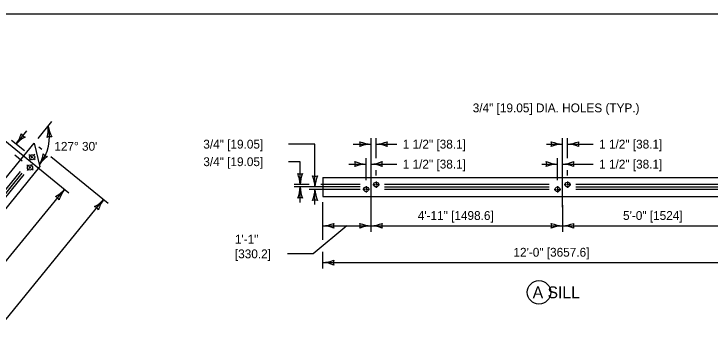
# Model space of a CAD drawing. Extents: x 49991.4 to 50021, y 49987.6 to 50011.4.
# Drawn here: x 50009.55 to 50014.286, y 49996.888 to 49998.999 of the extents above; entities that cross this region are included whole.
import ezdxf

# ---------------------------------------------------------------- set-up
doc = ezdxf.new("R2010")
doc.units = 0
for name, color, linetype in [('Level 1', 7, 'Continuous'), ('Level 2', 7, 'Continuous'), ('Level 3', 7, 'Continuous'), ('Level 5', 7, 'Continuous')]:
    doc.layers.add(name, color=color, linetype=linetype)

msp = doc.modelspace()

# ---------------------------------------------------------------- linework, layer by layer
at = {"layer": 'Level 1'}
for p, q in [((50007.4465, 49995.3728), (50009.6889, 49998.1205)), ((50009.6889, 49998.1205), (50009.7272, 49997.9577)), ((50007.5494, 49995.2888), (50009.7272, 49997.9577)), ((50007.6228, 49995.51), (50009.5947, 49997.926)), ((50007.6356, 49995.4996), (50009.6075, 49997.9156)), ((50007.6486, 49995.489), (50009.6203, 49997.9052)), ((50011.6513, 49997.8849), (50014.9124, 49997.8849)), ((50011.6513, 49997.8849), (50011.6513, 49997.7571)), ((50013.1902, 49997.8371), (50012.0707, 49997.8371)), ((50012.0707, 49997.8211), (50013.1902, 49997.8211)), ((50014.5603, 49997.8371), (50013.3735, 49997.8371)), ((50013.3735, 49997.8211), (50014.5603, 49997.8211)), ((50013.1902, 49997.8051), (50012.0707, 49997.8051)), ((50014.5603, 49997.8051), (50013.3735, 49997.8051)), ((50011.6513, 49997.7571), (50014.9124, 49997.7571))]:
    msp.add_line(p, q, dxfattribs=at)
msp.add_lwpolyline([(49999.3835, 49998.9992), (50016.7501, 49998.9992), (50016.7501, 49987.7988), (49999.3835, 49987.7988)], close=True, dxfattribs=at)
for centre in [(50009.6742, 49998.0234), (50009.6597, 49997.9536)]:
    msp.add_circle(centre, 0.0175, dxfattribs=at)
for centre in [(50011.9465, 49997.8052), (50012.0137, 49997.837), (50013.2479, 49997.8051), (50013.3158, 49997.837)]:
    msp.add_ellipse(centre, major_axis=(0.017, 0), ratio=0.940299, dxfattribs=at)
at = {"layer": 'Level 2'}
msp.add_circle((50013.1221, 49997.1041), 0.08, dxfattribs=at)
at = {"layer": 'Level 3'}
for p, q in [((50009.7142, 49998.1515), (50009.8086, 49998.2671)), ((50009.5648, 49998.1128), (50009.6385, 49998.2032)), ((50009.9245, 49997.7786), (50009.4364, 49998.1768)), ((50011.9797, 49997.5168), (50011.9797, 49998.1527)), ((50012.0136, 49998.0167), (50012.0136, 49998.1527)), ((50013.2819, 49997.9099), (50013.2819, 49998.1527)), ((50013.3159, 49998.0167), (50013.3159, 49998.1527)), ((50009.6219, 49998.0662), (50009.5339, 49998.1381)), ((50011.5984, 49998.1127), (50011.4187, 49998.1127)), ((50011.5984, 49997.9146), (50011.5984, 49998.1127)), ((50011.8575, 49998.1127), (50011.9797, 49998.1127)), ((50012.0136, 49998.1127), (50012.1551, 49998.1127)), ((50013.1729, 49998.1127), (50013.2819, 49998.1127)), ((50013.3159, 49998.1127), (50013.4911, 49998.1127)), ((50009.7199, 49998.0952), (50009.7402, 49998.0786)), ((50009.6074, 49997.9964), (50009.5559, 49998.0385)), ((50009.8022, 49998.028), (50010.1915, 49997.7104)), ((50011.9464, 49997.8664), (50011.9464, 49998.0167)), ((50013.2479, 49997.8664), (50013.2479, 49998.0167)), ((50011.4974, 49997.9931), (50011.4187, 49997.9931)), ((50011.4974, 49997.8371), (50011.4974, 49997.9931)), ((50011.8276, 49997.9767), (50011.9464, 49997.9767)), ((50011.9797, 49997.9767), (50012.1551, 49997.9767)), ((50013.1411, 49997.9767), (50013.2479, 49997.9767)), ((50013.2819, 49997.9767), (50013.4911, 49997.9767)), ((50011.5984, 49997.8211), (50011.5984, 49997.9146)), ((50012.0136, 49997.8983), (50012.0136, 49997.9367)), ((50013.2819, 49997.6836), (50013.2819, 49997.9099)), ((50013.3159, 49997.8983), (50013.3159, 49997.9367)), ((50011.5584, 49997.8371), (50011.4574, 49997.8371)), ((50011.9064, 49997.8211), (50011.4574, 49997.8211)), ((50011.4974, 49997.7156), (50011.4974, 49997.8211)), ((50011.9064, 49997.8371), (50011.6384, 49997.8371)), ((50007.8012, 49995.24), (50009.8935, 49997.8039)), ((50011.9064, 49997.8051), (50011.5584, 49997.8051)), ((50011.5984, 49997.7012), (50011.5984, 49997.8051)), ((50007.918, 49994.9878), (50010.1605, 49997.7357)), ((50011.6513, 49997.4608), (50011.6513, 49997.7171)), ((50013.2819, 49997.698), (50013.2819, 49997.5168)), ((50011.6513, 49997.5568), (50011.9797, 49997.5568)), ((50011.9797, 49997.5568), (50013.2819, 49997.5568)), ((50013.2819, 49997.5568), (50014.6407, 49997.5568)), ((50011.6513, 49997.2668), (50011.6513, 49997.3808)), ((50011.6513, 49997.3068), (50014.9124, 49997.3068))]:
    msp.add_line(p, q, dxfattribs=at)
msp.add_lwpolyline([(50011.8155, 49997.5568), (50011.585, 49997.3659), (50011.4116, 49997.3659)], dxfattribs=at)
for centre, radius, start, end in [((50009.5617, 49998.2185), 0.2223, 344.3666, 4.5501), ((50010.0129, 49998.2755), 0.233, 189.7379, 208.9878), ((50009.3772, 49998.251), 0.233, 323.6381, 342.888), ((50009.7312, 49997.9654), 0.2223, 118.2668, 138.4503), ((50009.6458, 49998.2122), 0.0548, 212.9496, 248.672), ((50009.7987, 49998.1088), 0.0548, 79.0494, 114.7718), ((50011.9889, 49998.3348), 0.2223, 247.456, 267.6395), ((50011.8515, 49998.1127), 0.0548, 342.1388, 17.8612), ((50011.9912, 49997.88), 0.233, 92.8273, 112.0772), ((50012.0021, 49998.3454), 0.233, 272.8273, 292.0772), ((50012.0044, 49997.8906), 0.2223, 67.456, 87.6395), ((50012.1418, 49998.1127), 0.0548, 162.1388, 197.8612), ((50013.2911, 49998.3348), 0.2223, 247.456, 267.6395), ((50013.1537, 49998.1127), 0.0548, 342.1388, 17.8612), ((50013.2934, 49997.88), 0.233, 92.8273, 112.0772), ((50013.3044, 49998.3454), 0.233, 272.8273, 292.0772), ((50013.3067, 49997.8906), 0.2223, 67.456, 87.6395), ((50013.4441, 49998.1127), 0.0548, 162.1388, 197.8612), ((50009.5214, 49998.0897), 0.233, 330.126, 349.3758), ((50009.9054, 49997.8459), 0.2223, 124.7547, 144.9382), ((50009.7927, 49998.0815), 0.0548, 219.4375, 255.1599), ((50011.9556, 49998.1988), 0.2223, 247.456, 267.6395), ((50011.8182, 49997.9767), 0.0548, 342.1388, 17.8612), ((50011.9579, 49997.744), 0.233, 92.8273, 112.0772), ((50011.9682, 49998.2094), 0.233, 272.8273, 292.0772), ((50011.9705, 49997.7546), 0.2223, 67.456, 87.6395), ((50012.1079, 49997.9767), 0.0548, 162.1388, 197.8612), ((50013.2571, 49998.1988), 0.2223, 247.456, 267.6395), ((50013.1197, 49997.9767), 0.0548, 342.1388, 17.8612), ((50013.2594, 49997.744), 0.233, 92.8273, 112.0772), ((50013.2704, 49998.2094), 0.233, 272.8273, 292.0772), ((50013.2727, 49997.7546), 0.2223, 67.456, 87.6395), ((50013.4101, 49997.9767), 0.0548, 162.1388, 197.8612), ((50011.4974, 49997.9653), 0.0548, 252.1388, 287.8612), ((50011.2647, 49997.8256), 0.233, 2.8273, 22.0772), ((50011.7195, 49997.8279), 0.2223, 157.456, 177.6395), ((50011.5984, 49997.9493), 0.0548, 252.1388, 287.8612), ((50011.3657, 49997.8096), 0.233, 2.8273, 22.0772), ((50011.8205, 49997.8119), 0.2223, 157.456, 177.6395), ((50011.2753, 49997.8303), 0.2223, 337.456, 357.6395), ((50011.7301, 49997.8326), 0.233, 182.8273, 202.0772), ((50009.7272, 49997.9514), 0.2223, 298.2386, 318.4221), ((50010.0811, 49997.6656), 0.233, 143.6099, 162.8597), ((50011.3763, 49997.8143), 0.2223, 337.456, 357.6395), ((50011.8311, 49997.8166), 0.233, 182.8273, 202.0772), ((50009.8125, 49997.7045), 0.0548, 32.9214, 68.6437), ((50009.9942, 49997.8832), 0.2223, 298.2384, 318.4219), ((50010.3481, 49997.5974), 0.233, 143.6097, 162.8595), ((50011.4974, 49997.6929), 0.0548, 72.1388, 107.8612), ((50011.5984, 49997.6769), 0.0548, 72.1388, 107.8612), ((50010.0795, 49997.6363), 0.0548, 32.9212, 68.6435), ((50011.6398, 49997.7895), 0.233, 272.8273, 292.0772), ((50011.6421, 49997.3347), 0.2223, 67.456, 87.6395), ((50011.7795, 49997.5568), 0.0548, 162.1388, 197.8612), ((50011.9889, 49997.7789), 0.2223, 247.456, 267.6395), ((50011.8515, 49997.5568), 0.0548, 342.1388, 17.8612), ((50011.9912, 49997.3241), 0.233, 92.8273, 112.0772), ((50011.9682, 49997.7895), 0.233, 272.8273, 292.0772), ((50011.9705, 49997.3347), 0.2223, 67.456, 87.6395), ((50012.1079, 49997.5568), 0.0548, 162.1388, 197.8612), ((50013.2911, 49997.7789), 0.2223, 247.456, 267.6395), ((50013.1537, 49997.5568), 0.0548, 342.1388, 17.8612), ((50013.2934, 49997.3241), 0.233, 92.8273, 112.0772), ((50013.2704, 49997.7895), 0.233, 272.8273, 292.0772), ((50013.2727, 49997.3347), 0.2223, 67.456, 87.6395), ((50013.4101, 49997.5568), 0.0548, 162.1388, 197.8612), ((50011.6398, 49997.5395), 0.233, 272.8273, 292.0772), ((50011.6421, 49997.0847), 0.2223, 67.456, 87.6395), ((50011.7795, 49997.3068), 0.0548, 162.1388, 197.8612)]:
    msp.add_arc(centre, radius, start, end, dxfattribs=at)
msp.add_ellipse((50009.4643, 49998.163), major_axis=(0.3284, 0), ratio=0.938809, start_param=5.621944, end_param=6.522685, dxfattribs=at)
at = {"layer": 'Level 5'}
for p, q in [((50009.6645, 49998.0314), (50009.6529, 49998.0409)), ((50009.6568, 49998.0022), (50009.6663, 49998.0138)), ((50009.68, 49998.0187), (50009.6684, 49998.0282)), ((50009.6695, 49998.0177), (50009.679, 49998.0293)), ((50009.6822, 49998.0332), (50009.6917, 49998.0448)), ((50009.6955, 49998.006), (50009.6839, 49998.0155)), ((50009.65, 49997.9616), (50009.6384, 49997.9711)), ((50009.6655, 49997.9489), (50009.6539, 49997.9584)), ((50009.655, 49997.9479), (50009.6645, 49997.9595)), ((50009.6677, 49997.9634), (50009.6772, 49997.975)), ((50009.6423, 49997.9324), (50009.6518, 49997.944)), ((50009.681, 49997.9362), (50009.6694, 49997.9457)), ((50011.9464, 49997.8264), (50011.9464, 49997.8126)), ((50011.991, 49997.8371), (50012.0057, 49997.8371)), ((50012.0093, 49997.8371), (50012.0186, 49997.8371)), ((50012.0136, 49997.8583), (50012.0136, 49997.8445)), ((50012.0136, 49997.842), (50012.0136, 49997.8328)), ((50012.0136, 49997.8295), (50012.0136, 49997.8158)), ((50012.0216, 49997.8371), (50012.0363, 49997.8371)), ((50013.2479, 49997.8264), (50013.2479, 49997.8125)), ((50013.2932, 49997.8371), (50013.3079, 49997.8371)), ((50013.3114, 49997.8371), (50013.3208, 49997.8371)), ((50013.3159, 49997.8583), (50013.3159, 49997.8445)), ((50013.3159, 49997.842), (50013.3159, 49997.8328)), ((50013.3159, 49997.8295), (50013.3159, 49997.8158)), ((50013.3238, 49997.8371), (50013.3385, 49997.8371)), ((50011.9238, 49997.8052), (50011.9385, 49997.8052)), ((50011.9421, 49997.8052), (50011.9515, 49997.8052)), ((50011.9464, 49997.8103), (50011.9464, 49997.8011)), ((50011.9464, 49997.7977), (50011.9464, 49997.7839)), ((50011.9544, 49997.8052), (50011.9691, 49997.8052)), ((50013.2252, 49997.8051), (50013.2399, 49997.8051)), ((50013.2436, 49997.8051), (50013.2528, 49997.8051)), ((50013.2479, 49997.81), (50013.2479, 49997.8009)), ((50013.2479, 49997.7977), (50013.2479, 49997.7838)), ((50013.2558, 49997.8051), (50013.2705, 49997.8051))]:
    msp.add_line(p, q, dxfattribs=at)

# ---------------------------------------------------------------- texts
at = {"layer": 'Level 2'}
for s, height, p in [('3/4" [19.05] DIA. HOLES (TYP.)', 0.06, (50012.6715, 49998.3295)), ('3/4" [19.05]', 0.06, (50010.8387, 49998.0827)), ('1 1/2" [38.1]', 0.06, (50012.1951, 49998.0827)), ('1 1/2" [38.1]', 0.06, (50013.5311, 49998.0827)), ("127° 30'", 0.06, (50009.8252, 49998.0677)), ('3/4" [19.05]', 0.06, (50010.8387, 49997.9631)), ('1 1/2" [38.1]', 0.06, (50012.1951, 49997.9467)), ('1 1/2" [38.1]', 0.06, (50013.5311, 49997.9467)), ('4\'-11" [1498.6]', 0.06, (50012.2975, 49997.5968)), ('5\'-0" [1524]', 0.06, (50013.6938, 49997.5968)), ('1\'-1"', 0.06, (50011.0536, 49997.4359)), ('[330.2]', 0.06, (50011.0536, 49997.3359)), ('12\'-0" [3657.6]', 0.06, (50012.9485, 49997.3468)), ('A SILL', 0.08, (50013.0792, 49997.0641))]:
    msp.add_text(s, height=height, dxfattribs=at).set_placement(p)

doc.saveas('drawing.dxf')
